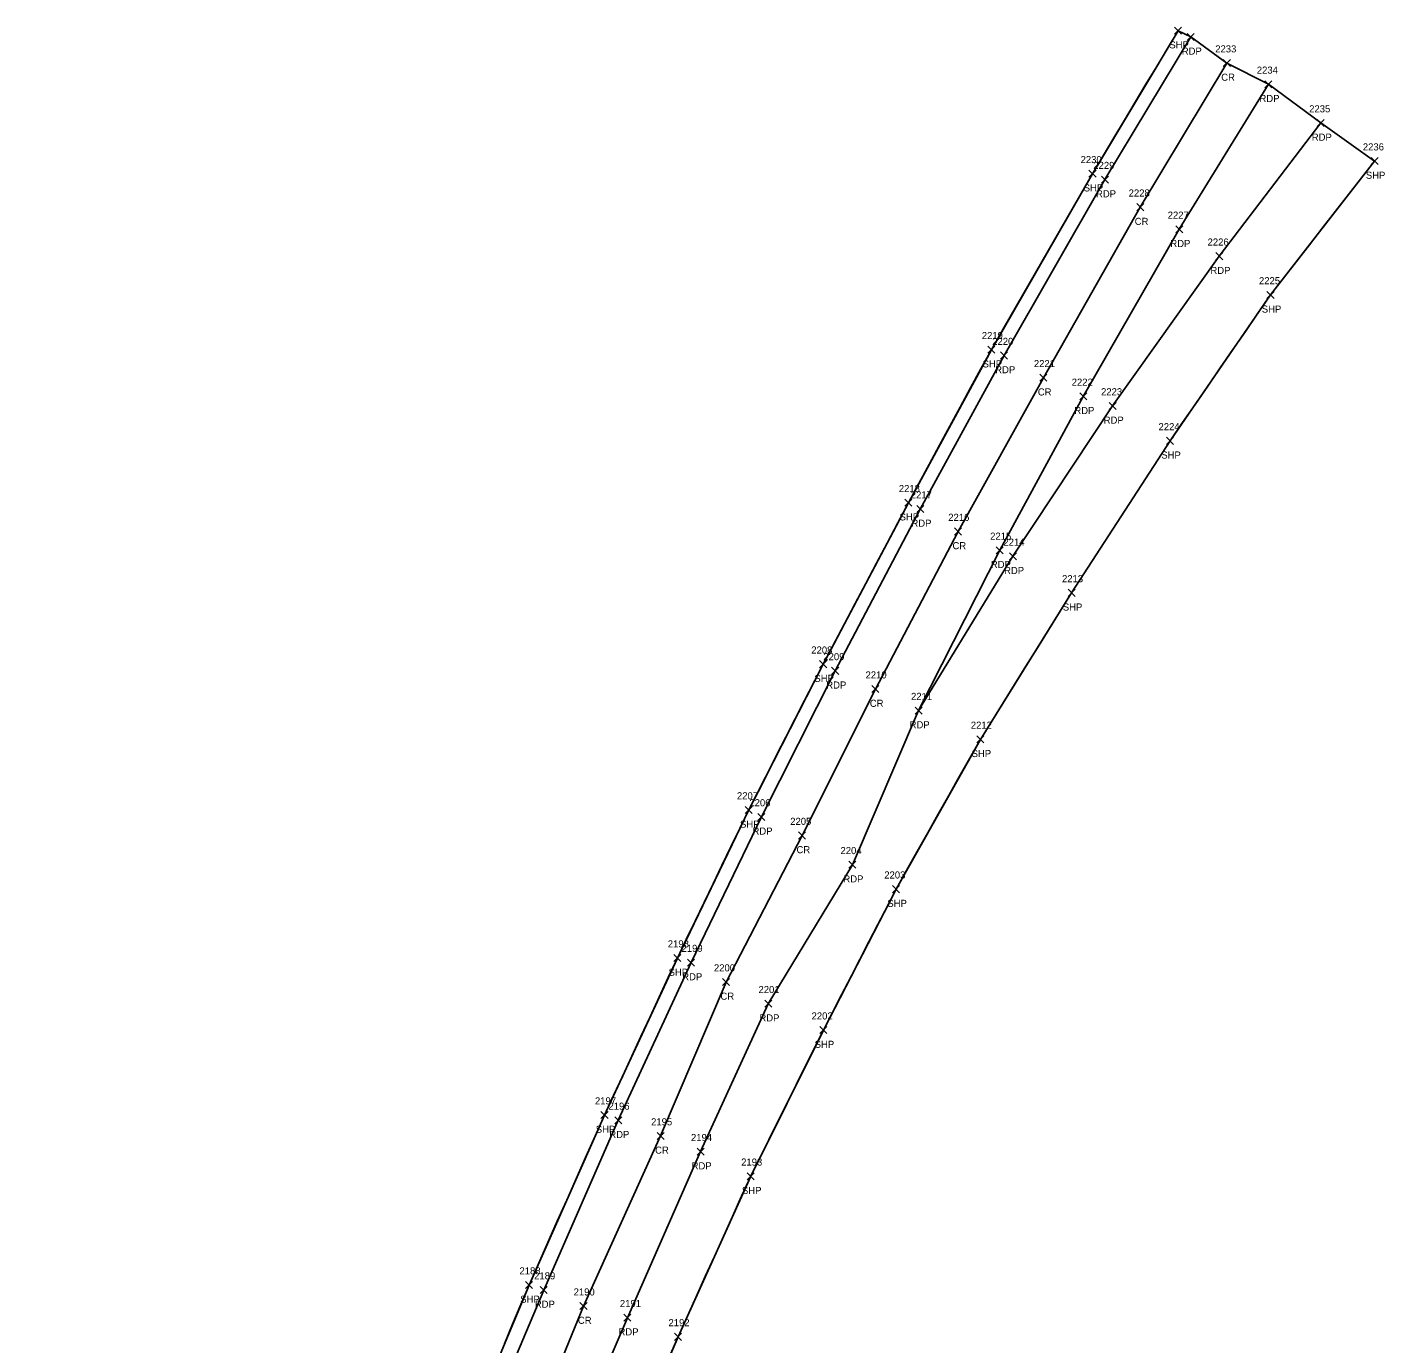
# Model space of a CAD drawing. Extents: x 1688195 to 1692013, y 424605 to 441234.
# Drawn here: x 1690771.1 to 1691154.1, y 438288.1 to 438659.6 of the extents above; entities that cross this region are included whole.
import ezdxf

# ---------------------------------------------------------------- set-up
doc = ezdxf.new("R2010")
doc.units = 0
for name, color, linetype in [('LSOGP', 7, 'Continuous'), ('P_A', 7, 'Continuous'), ('P_I', 7, 'Continuous'), ('P_TIC', 7, 'Continuous'), ('PET', 7, 'Continuous'), ('PRC', 7, 'Continuous'), ('PSP', 7, 'Continuous')]:
    doc.layers.add(name, color=color, linetype=linetype)

msp = doc.modelspace()

# ---------------------------------------------------------------- linework, layer by layer
at = {"layer": 'LSOGP'}
msp.add_lwpolyline([(1690952.24, 438284.41), (1690954.7, 438290.11), (1690957.26, 438295.77), (1690959.83, 438301.43), (1690962.39, 438307.1), (1690964.95, 438312.76), (1690967.52, 438318.42), (1690970.08, 438324.08), (1690972.64, 438329.74), (1690975.21, 438335.41), (1690977.77, 438340.56), (1690980.33, 438345.71), (1690982.9, 438350.87), (1690985.46, 438356.02), (1690988.02, 438361.17), (1690990.58, 438366.33), (1690993.15, 438371.48), (1690995.71, 438376.63), (1690998.27, 438381.6), (1691000.84, 438386.58), (1691003.4, 438391.55), (1691005.96, 438396.52), (1691008.53, 438401.49), (1691011.09, 438406.46), (1691013.66, 438411.43), (1691016.22, 438416.4), (1691019.19, 438421.68), (1691022.16, 438426.97), (1691025.13, 438432.25), (1691028.1, 438437.53), (1691031.07, 438442.81), (1691034.04, 438448.09), (1691037.01, 438453.37), (1691039.98, 438458.65), (1691043.2, 438463.82), (1691046.41, 438468.99), (1691049.63, 438474.16), (1691052.85, 438479.32), (1691056.06, 438484.49), (1691059.28, 438489.66), (1691062.5, 438494.83), (1691065.71, 438499.99), (1691069.19, 438505.35), (1691072.66, 438510.71), (1691076.13, 438516.07), (1691079.61, 438521.43), (1691083.08, 438526.78), (1691086.55, 438532.14), (1691090.03, 438537.5), (1691093.5, 438542.86), (1691097.04, 438548.01), (1691100.58, 438553.15), (1691104.13, 438558.3), (1691107.67, 438563.45), (1691111.21, 438568.6), (1691114.76, 438573.75), (1691118.3, 438578.89), (1691121.84, 438584.04), (1691125.51, 438588.76), (1691129.18, 438593.48), (1691132.85, 438598.2), (1691136.52, 438602.92), (1691140.18, 438607.64), (1691143.85, 438612.36), (1691147.52, 438617.07), (1691151.19, 438621.79), (1691136, 438632.53), (1691121.23, 438643.45), (1691109.5, 438649.44), (1691099.31, 438656.81), (1691095.76, 438658.57), (1691092.74, 438653.52), (1691089.72, 438648.48), (1691086.7, 438643.44), (1691083.68, 438638.39), (1691080.66, 438633.35), (1691077.64, 438628.31), (1691074.63, 438623.26), (1691071.61, 438618.22), (1691068.04, 438612.01), (1691064.48, 438605.81), (1691060.91, 438599.6), (1691057.35, 438593.39), (1691053.78, 438587.19), (1691050.22, 438580.98), (1691046.65, 438574.78), (1691043.09, 438568.57), (1691040.16, 438563.18), (1691037.24, 438557.78), (1691034.31, 438552.39), (1691031.38, 438546.99), (1691028.46, 438541.6), (1691025.53, 438536.2), (1691022.6, 438530.81), (1691019.67, 438525.41), (1691016.67, 438519.72), (1691013.66, 438514.02), (1691010.66, 438508.33), (1691007.65, 438502.63), (1691004.65, 438496.94), (1691001.64, 438491.25), (1690998.64, 438485.55), (1690995.63, 438479.86), (1690993.01, 438474.72), (1690990.39, 438469.58), (1690987.77, 438464.44), (1690985.15, 438459.3), (1690982.52, 438454.16), (1690979.9, 438449.02), (1690977.28, 438443.88), (1690974.66, 438438.74), (1690972.14, 438433.52), (1690969.62, 438428.3), (1690967.1, 438423.07), (1690964.58, 438417.85), (1690962.06, 438412.63), (1690959.54, 438407.41), (1690957.03, 438402.19), (1690954.51, 438396.96), (1690951.94, 438391.43), (1690949.37, 438385.89), (1690946.8, 438380.35), (1690944.23, 438374.82), (1690941.67, 438369.28), (1690939.1, 438363.74), (1690936.53, 438358.21), (1690933.96, 438352.67), (1690931.3, 438346.68), (1690928.64, 438340.68), (1690925.98, 438334.69), (1690923.32, 438328.7), (1690920.65, 438322.7), (1690917.99, 438316.71), (1690915.33, 438310.72), (1690912.67, 438304.72), (1690910.35, 438299.18), (1690908.04, 438293.65), (1690905.73, 438288.11)], dxfattribs=at)
at = {"layer": 'P_TIC'}
for points in [[(1691094.76, 438657.57), (1691096.76, 438659.57)], [(1691096.76, 438657.57), (1691094.76, 438659.57)], [(1691098.31, 438655.81), (1691100.31, 438657.81)], [(1691100.31, 438655.81), (1691098.31, 438657.81)], [(1691108.5, 438648.44), (1691110.5, 438650.44)], [(1691110.5, 438648.44), (1691108.5, 438650.44)], [(1691120.23, 438642.45), (1691122.23, 438644.45)], [(1691122.23, 438642.45), (1691120.23, 438644.45)], [(1691135, 438631.53), (1691137, 438633.53)], [(1691137, 438631.53), (1691135, 438633.53)], [(1691150.19, 438620.79), (1691152.19, 438622.79)], [(1691152.19, 438620.79), (1691150.19, 438622.79)], [(1691070.61, 438617.22), (1691072.61, 438619.22)], [(1691072.61, 438617.22), (1691070.61, 438619.22)], [(1691074.12, 438615.57), (1691076.12, 438617.57)], [(1691076.12, 438615.57), (1691074.12, 438617.57)], [(1691084.08, 438607.78), (1691086.08, 438609.78)], [(1691086.08, 438607.78), (1691084.08, 438609.78)], [(1691095.09, 438601.54), (1691097.09, 438603.54)], [(1691097.09, 438601.54), (1691095.09, 438603.54)], [(1691106.39, 438593.95), (1691108.39, 438595.95)], [(1691108.39, 438593.95), (1691106.39, 438595.95)], [(1691120.84, 438583.04), (1691122.84, 438585.04)], [(1691122.84, 438583.04), (1691120.84, 438585.04)], [(1691042.09, 438567.57), (1691044.09, 438569.57)], [(1691044.09, 438567.57), (1691042.09, 438569.57)], [(1691045.68, 438565.93), (1691047.68, 438567.93)], [(1691047.68, 438565.93), (1691045.68, 438567.93)], [(1691056.77, 438559.66), (1691058.77, 438561.66)], [(1691058.77, 438559.66), (1691056.77, 438561.66)], [(1691068.01, 438554.42), (1691070.01, 438556.42)], [(1691070.01, 438554.42), (1691068.01, 438556.42)], [(1691076.29, 438551.71), (1691078.29, 438553.71)], [(1691078.29, 438551.71), (1691076.29, 438553.71)], [(1691092.5, 438541.86), (1691094.5, 438543.86)], [(1691094.5, 438541.86), (1691092.5, 438543.86)], [(1691018.67, 438524.41), (1691020.67, 438526.41)], [(1691020.67, 438524.41), (1691018.67, 438526.41)], [(1691022.05, 438522.63), (1691024.05, 438524.63)], [(1691024.05, 438522.63), (1691022.05, 438524.63)], [(1691032.68, 438516.29), (1691034.68, 438518.29)], [(1691034.68, 438516.29), (1691032.68, 438518.29)], [(1691044.45, 438510.99), (1691046.45, 438512.99)], [(1691046.45, 438510.99), (1691044.45, 438512.99)], [(1691048.18, 438509.29), (1691050.18, 438511.29)], [(1691050.18, 438509.29), (1691048.18, 438511.29)], [(1691064.71, 438498.99), (1691066.71, 438500.99)], [(1691066.71, 438498.99), (1691064.71, 438500.99)], [(1690994.63, 438478.86), (1690996.63, 438480.86)], [(1690996.63, 438478.86), (1690994.63, 438480.86)], [(1690998.03, 438476.98), (1691000.03, 438478.98)], [(1691000.03, 438476.98), (1690998.03, 438478.98)], [(1691009.38, 438471.83), (1691011.38, 438473.83)], [(1691011.38, 438471.83), (1691009.38, 438473.83)], [(1691021.56, 438465.77), (1691023.56, 438467.77)], [(1691023.56, 438465.77), (1691021.56, 438467.77)], [(1691021.56, 438465.77), (1691023.56, 438467.77)], [(1691023.56, 438465.77), (1691021.56, 438467.77)], [(1691038.98, 438457.65), (1691040.98, 438459.65)], [(1691040.98, 438457.65), (1691038.98, 438459.65)], [(1690973.66, 438437.74), (1690975.66, 438439.74)], [(1690975.66, 438437.74), (1690973.66, 438439.74)], [(1690977.22, 438435.78), (1690979.22, 438437.78)], [(1690979.22, 438435.78), (1690977.22, 438437.78)], [(1690988.69, 438430.53), (1690990.69, 438432.53)], [(1690990.69, 438430.53), (1690988.69, 438432.53)], [(1691002.87, 438422.28), (1691004.87, 438424.28)], [(1691004.87, 438422.28), (1691002.87, 438424.28)], [(1691015.22, 438415.4), (1691017.22, 438417.4)], [(1691017.22, 438415.4), (1691015.22, 438417.4)], [(1690953.51, 438395.96), (1690955.51, 438397.96)], [(1690955.51, 438395.96), (1690953.51, 438397.96)], [(1690957.39, 438394.69), (1690959.39, 438396.69)], [(1690959.39, 438394.69), (1690957.39, 438396.69)], [(1690967.25, 438389.19), (1690969.25, 438391.19)], [(1690969.25, 438389.19), (1690967.25, 438391.19)], [(1690979.17, 438383.07), (1690981.17, 438385.07)], [(1690981.17, 438383.07), (1690979.17, 438385.07)], [(1690994.71, 438375.63), (1690996.71, 438377.63)], [(1690996.71, 438375.63), (1690994.71, 438377.63)], [(1690932.96, 438351.67), (1690934.96, 438353.67)], [(1690934.96, 438351.67), (1690932.96, 438353.67)], [(1690936.83, 438350.19), (1690938.83, 438352.19)], [(1690938.83, 438350.19), (1690936.83, 438352.19)], [(1690948.8, 438345.77), (1690950.8, 438347.77)], [(1690950.8, 438345.77), (1690948.8, 438347.77)], [(1690960.06, 438341.34), (1690962.06, 438343.34)], [(1690962.06, 438341.34), (1690960.06, 438343.34)], [(1690974.21, 438334.41), (1690976.21, 438336.41)], [(1690976.21, 438334.41), (1690974.21, 438336.41)], [(1690911.67, 438303.72), (1690913.67, 438305.72)], [(1690913.67, 438303.72), (1690911.67, 438305.72)], [(1690915.82, 438302.31), (1690917.82, 438304.31)], [(1690917.82, 438302.31), (1690915.82, 438304.31)], [(1690927.03, 438297.77), (1690929.03, 438299.77)], [(1690929.03, 438297.77), (1690927.03, 438299.77)], [(1690939.42, 438294.51), (1690941.42, 438296.51)], [(1690941.42, 438294.51), (1690939.42, 438296.51)], [(1690953.7, 438289.11), (1690955.7, 438291.11)], [(1690955.7, 438289.11), (1690953.7, 438291.11)]]:
    msp.add_lwpolyline(points, dxfattribs=at)
at = {"layer": 'PET'}
for points in [[(1690775.14, 437892.19), (1690786.57, 437936.04), (1690799.79, 437981.42), (1690814.04, 438027.77), (1690829.21, 438075.33), (1690845.85, 438122.83), (1690862.79, 438169.47), (1690880.38, 438214.59), (1690898.07, 438258.78), (1690916.82, 438303.31), (1690937.83, 438351.19), (1690958.39, 438395.69), (1690978.22, 438436.78), (1690999.03, 438477.98), (1691023.05, 438523.63), (1691046.68, 438566.93), (1691075.12, 438616.57), (1691099.31, 438656.81)], [(1691022.56, 438466.77), (1691045.45, 438511.99), (1691069.01, 438555.42), (1691096.09, 438602.54), (1691121.23, 438643.45)], [(1690799.47, 437885.38), (1690811.72, 437928.04), (1690824.23, 437974.49), (1690837.32, 438020.05), (1690852.48, 438066.89), (1690868.89, 438114.64), (1690886.3, 438161.47), (1690903.29, 438205.6), (1690920.79, 438249.76), (1690940.42, 438295.51), (1690961.06, 438342.34), (1690980.17, 438384.07), (1691003.87, 438423.28), (1691022.56, 438466.77), (1691049.18, 438510.29), (1691077.29, 438552.71), (1691107.39, 438594.95), (1691136, 438632.53)]]:
    msp.add_lwpolyline(points, dxfattribs=at)
at = {"layer": 'PRC'}
msp.add_lwpolyline([(1690787.43, 437889.13), (1690798.27, 437931.55), (1690811.79, 437978.12), (1690825.18, 438023.45), (1690840.98, 438071), (1690857.12, 438117.88), (1690874.77, 438165.68), (1690891.05, 438208.77), (1690909.76, 438254.18), (1690928.03, 438298.77), (1690949.8, 438346.77), (1690968.25, 438390.19), (1690989.69, 438431.53), (1691010.38, 438472.83), (1691033.68, 438517.29), (1691057.77, 438560.66), (1691085.08, 438608.78), (1691109.5, 438649.44)], dxfattribs=at)
at = {"layer": 'PSP'}
for points in [[(1690771.1, 437893.4), (1690782.23, 437936.63), (1690795.5, 437982.76), (1690809.47, 438028.77), (1690825.08, 438076.38), (1690841.35, 438123.92), (1690858.95, 438170.7), (1690876.31, 438216.07), (1690894.16, 438260.41), (1690912.67, 438304.72), (1690933.96, 438352.67), (1690954.51, 438396.96), (1690974.66, 438438.74), (1690995.63, 438479.86), (1691019.67, 438525.41), (1691043.09, 438568.57), (1691071.61, 438618.22), (1691095.76, 438658.57)], [(1690809.46, 437882.47), (1690820.87, 437925.64), (1690833.81, 437971.31), (1690848.07, 438016.96), (1690863.79, 438062.1), (1690881.24, 438110.03), (1690899.21, 438156.7), (1690916.65, 438200.72), (1690935.03, 438244.51), (1690954.7, 438290.11), (1690975.21, 438335.41), (1690995.71, 438376.63), (1691016.22, 438416.4), (1691039.98, 438458.65), (1691065.71, 438499.99), (1691093.5, 438542.86), (1691121.84, 438584.04), (1691151.19, 438621.79)]]:
    msp.add_lwpolyline(points, dxfattribs=at)

# ---------------------------------------------------------------- texts
at = {"layer": 'P_A'}
for s, p in [('SHP', (1691093.3, 438653.57)), ('RDP', (1691096.8, 438651.81)), ('CR', (1691107.93, 438644.44)), ('RDP', (1691118.72, 438638.45)), ('RDP', (1691133.48, 438627.53)), ('SHP', (1691148.73, 438616.79)), ('SHP', (1691069.14, 438613.22)), ('RDP', (1691072.61, 438611.57)), ('CR', (1691083.52, 438603.78)), ('RDP', (1691093.58, 438597.54)), ('RDP', (1691104.88, 438589.95)), ('SHP', (1691119.38, 438579.04)), ('SHP', (1691040.62, 438563.57)), ('RDP', (1691044.17, 438561.93)), ('CR', (1691056.2, 438555.66)), ('RDP', (1691066.5, 438550.42)), ('RDP', (1691074.78, 438547.71)), ('SHP', (1691091.03, 438537.86)), ('SHP', (1691017.21, 438520.41)), ('RDP', (1691020.54, 438518.63)), ('CR', (1691032.12, 438512.29)), ('RDP', (1691042.94, 438506.99)), ('RDP', (1691046.67, 438505.29)), ('SHP', (1691063.25, 438494.99)), ('SHP', (1690993.17, 438474.86)), ('RDP', (1690996.52, 438472.98)), ('CR', (1691008.81, 438467.83)), ('RDP', (1691020.04, 438461.77)), ('RDP', (1691020.04, 438461.77)), ('SHP', (1691037.52, 438453.65)), ('SHP', (1690972.19, 438433.74)), ('RDP', (1690975.71, 438431.78)), ('CR', (1690988.12, 438426.53)), ('RDP', (1691001.35, 438418.28)), ('SHP', (1691013.75, 438411.4)), ('SHP', (1690952.04, 438391.96)), ('RDP', (1690955.88, 438390.69)), ('CR', (1690966.68, 438385.19)), ('RDP', (1690977.66, 438379.07)), ('SHP', (1690993.25, 438371.63)), ('SHP', (1690931.5, 438347.67)), ('RDP', (1690935.32, 438346.19)), ('CR', (1690948.23, 438341.77)), ('RDP', (1690958.54, 438337.34)), ('SHP', (1690972.74, 438330.41)), ('SHP', (1690910.2, 438299.72)), ('RDP', (1690914.31, 438298.31)), ('CR', (1690926.46, 438293.77)), ('RDP', (1690937.91, 438290.51))]:
    msp.add_text(s, height=2, dxfattribs=at).set_placement(p)
at = {"layer": 'P_I'}
for s, p in [('2233', (1691106.24, 438652.44)), ('2234', (1691117.97, 438646.45)), ('2235', (1691132.74, 438635.53)), ('2236', (1691147.88, 438624.79)), ('2230', (1691068.26, 438621.22)), ('2229', (1691071.85, 438619.57)), ('2228', (1691081.82, 438611.78)), ('2227', (1691092.83, 438605.54)), ('2226', (1691104.08, 438597.95)), ('2225', (1691118.58, 438587.04)), ('2219', (1691040.39, 438571.57)), ('2220', (1691043.33, 438569.93)), ('2221', (1691055.08, 438563.66)), ('2222', (1691065.75, 438558.42)), ('2223', (1691074.03, 438555.71)), ('2224', (1691090.24, 438545.86)), ('2218', (1691016.98, 438528.41)), ('2217', (1691020.36, 438526.63)), ('2216', (1691030.93, 438520.29)), ('2215', (1691042.75, 438514.99)), ('2214', (1691046.49, 438513.29)), ('2213', (1691063.02, 438502.99)), ('2208', (1690992.29, 438482.86)), ('2209', (1690995.69, 438480.98)), ('2210', (1691007.6, 438475.83)), ('2211', (1691020.43, 438469.77)), ('2211', (1691020.43, 438469.77)), ('2212', (1691037.29, 438461.65)), ('2207', (1690971.32, 438441.74)), ('2206', (1690974.83, 438439.78)), ('2205', (1690986.35, 438434.53)), ('2204', (1691000.53, 438426.28)), ('2203', (1691012.88, 438419.4)), ('2198', (1690951.81, 438399.96)), ('2199', (1690955.69, 438398.69)), ('2200', (1690964.83, 438393.19)), ('2201', (1690977.4, 438387.07)), ('2202', (1690992.37, 438379.63)), ('2197', (1690931.27, 438355.67)), ('2196', (1690935.08, 438354.19)), ('2195', (1690947.11, 438349.77)), ('2194', (1690958.36, 438345.34)), ('2193', (1690972.51, 438338.41)), ('2188', (1690909.98, 438307.72)), ('2189', (1690914.12, 438306.31)), ('2190', (1690925.25, 438301.77)), ('2191', (1690938.3, 438298.51)), ('2192', (1690952.01, 438293.11))]:
    msp.add_text(s, height=2, dxfattribs=at).set_placement(p)

doc.saveas('drawing.dxf')
